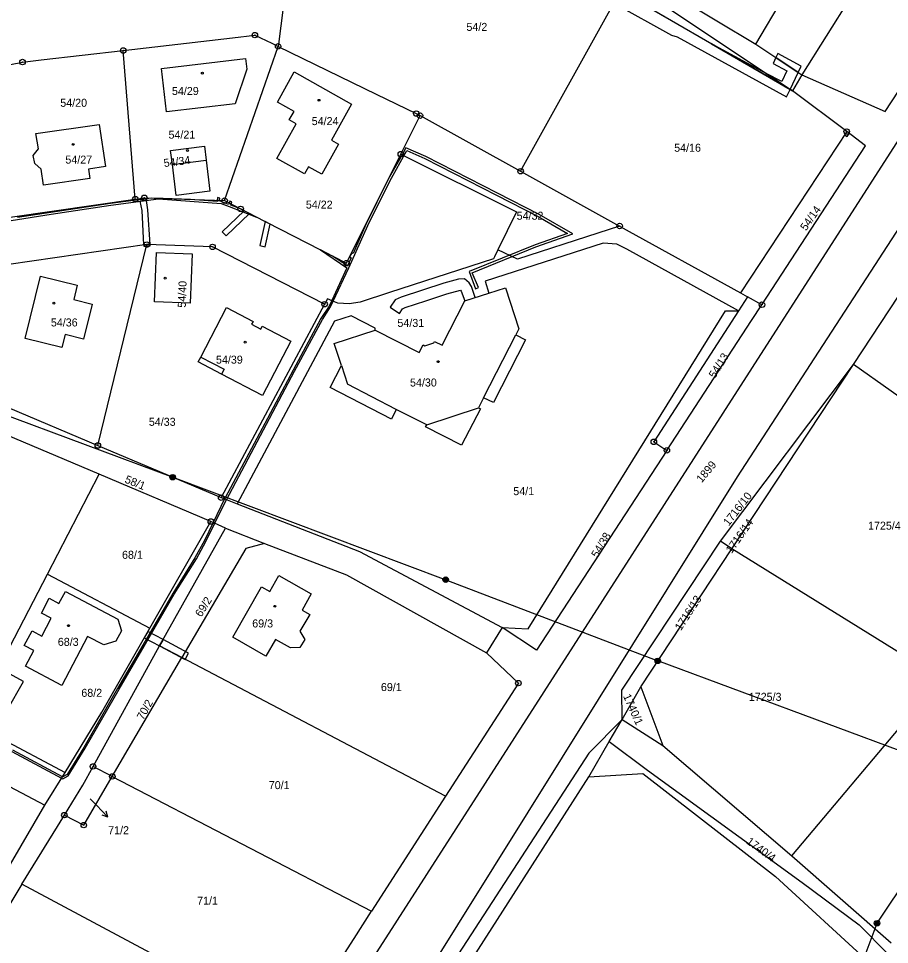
# Model space of a CAD drawing. Extents: x -587171 to -555306, y -1167727 to -1074732.
# Drawn here: x -559493.9 to -559335, y -1076599.6 to -1076430.8 of the extents above; entities that cross this region are included whole.
import ezdxf

# ---------------------------------------------------------------- set-up
doc = ezdxf.new("R2010")
doc.units = 0
for name, color, linetype in [('Hranice parcel', 7, 'Continuous'), ('Parcelní čísla', 7, 'Continuous'), ('Pop  PČ popisy', 7, 'Continuous'), ('Poz předměty', 7, 'Continuous'), ('Vnitřní kresba', 7, 'Continuous'), ('Věcná břemena k části', 7, 'Continuous'), ('Značky bodu BP', 7, 'Continuous'), ('Značky budov', 7, 'Continuous')]:
    doc.layers.add(name, color=color, linetype=linetype)

msp = doc.modelspace()

# ---------------------------------------------------------------- linework, layer by layer
at = {"layer": 'Hranice parcel'}
for p, q in [((-559295.54, -1076353.12), (-559351, -1076441.05)), ((-559359.39, -1076435.43), (-559344.86, -1076411.02)), ((-559385.89, -1076419.53), (-559359.39, -1076435.43)), ((-559352.65, -1076443.99), (-559384.02, -1076425.8)), ((-559456.26, -1076463.98), (-559446.5, -1076435.86)), ((-559359.39, -1076435.43), (-559351, -1076441.05)), ((-559472.55, -1076463.7), (-559474.75, -1076436.61)), ((-559351, -1076441.05), (-559352.65, -1076443.99)), ((-559342.79, -1076451.39), (-559352.65, -1076443.99)), ((-559424.11, -1076455.5), (-559420.61, -1076448.48)), ((-559420.61, -1076448.48), (-559402.27, -1076458.62)), ((-559342.79, -1076451.39), (-559362.14, -1076480.8)), ((-559402.27, -1076458.62), (-559384.2, -1076468.61)), ((-559495.36, -1076466.98), (-559472.55, -1076463.7)), ((-559384.2, -1076468.61), (-559362.14, -1076480.8)), ((-559479.38, -1076508.61), (-559470.45, -1076471.98)), ((-559362.52, -1076484.05), (-559382.91, -1076472.81)), ((-559360.87, -1076481.5), (-559362.52, -1076484.05)), ((-559362.14, -1076480.8), (-559360.87, -1076481.5)), ((-559358.25, -1076482.95), (-559360.87, -1076481.5)), ((-559438.02, -1076482.86), (-559456.89, -1076518.11)), ((-559400.9, -1076542.04), (-559364.92, -1076484.04)), ((-559364.92, -1076484.04), (-559362.52, -1076484.05)), ((-559365.81, -1076526.07), (-559341.55, -1076493.82)), ((-559363.74, -1076527.45), (-559341.55, -1076493.82)), ((-559495.73, -1076501.71), (-559479.38, -1076508.61)), ((-559479.13, -1076513.85), (-559497.95, -1076505.9)), ((-559479.38, -1076508.61), (-559456.89, -1076518.11)), ((-559488.54, -1076532.04), (-559479.13, -1076513.85)), ((-559458.77, -1076522.46), (-559479.13, -1076513.85)), ((-559453.98, -1076519.24), (-559431.64, -1076527.9)), ((-559469.9, -1076541.88), (-559458.77, -1076522.46)), ((-559468.14, -1076545.12), (-559456.12, -1076523.7)), ((-559456.12, -1076523.7), (-559458.77, -1076522.46)), ((-559456.12, -1076523.7), (-559448.96, -1076526.46)), ((-559448.96, -1076526.46), (-559452.38, -1076527.38)), ((-559448.96, -1076526.46), (-559434.02, -1076532.21)), ((-559363.74, -1076527.45), (-559365.81, -1076526.07)), ((-559452.38, -1076527.38), (-559464.04, -1076547.27)), ((-559431.64, -1076527.9), (-559405.64, -1076541.81)), ((-559380.33, -1076552.58), (-559363.74, -1076527.45)), ((-559325.62, -1076551.11), (-559363.74, -1076527.45)), ((-559496.26, -1076546.97), (-559488.54, -1076532.04)), ((-559488.54, -1076532.04), (-559469.9, -1076541.88)), ((-559434.02, -1076532.21), (-559408.49, -1076546.42)), ((-559405.64, -1076541.81), (-559408.49, -1076546.42)), ((-559405.64, -1076541.81), (-559400.9, -1076542.04)), ((-559480.25, -1076567.11), (-559468.14, -1076545.12)), ((-559464.04, -1076547.27), (-559468.14, -1076545.12)), ((-559476.74, -1076568.93), (-559464.04, -1076547.27)), ((-559415.94, -1076572.52), (-559464.04, -1076547.27)), ((-559352.77, -1076583.43), (-559325.62, -1076551.11)), ((-559383.77, -1076558.53), (-559380.33, -1076552.58)), ((-559380.33, -1076552.58), (-559376.32, -1076563.3)), ((-559502.55, -1076559.13), (-559485.32, -1076568.19)), ((-559386.1, -1076562.58), (-559383.77, -1076558.53)), ((-559383.77, -1076558.53), (-559376.32, -1076563.3)), ((-559389.81, -1076569), (-559386.1, -1076562.58)), ((-559376.32, -1076563.3), (-559352.77, -1076583.43)), ((-559505.11, -1076565.7), (-559489.07, -1076574.14)), ((-559476.74, -1076568.93), (-559480.25, -1076567.11)), ((-559489.07, -1076574.14), (-559485.32, -1076568.19)), ((-559481.94, -1076577.8), (-559476.74, -1076568.93)), ((-559476.74, -1076568.93), (-559429.44, -1076593.49)), ((-559444.21, -1076653.89), (-559389.81, -1076569)), ((-559415.94, -1076572.52), (-559429.44, -1076593.49)), ((-559503.32, -1076598.59), (-559489.07, -1076574.14)), ((-559493.23, -1076588.57), (-559485.49, -1076575.98)), ((-559485.49, -1076575.98), (-559481.94, -1076577.8)), ((-559352.77, -1076583.43), (-559334.65, -1076599.27)), ((-559493.23, -1076588.57), (-559507.12, -1076611.45)), ((-559443.38, -1076615.16), (-559493.23, -1076588.57))]:
    msp.add_line(p, q, dxfattribs=at)
for points in [[(-559351, -1076441.05), (-559335.79, -1076447.71), (-559279.35, -1076361.68)], [(-559607.03, -1076893.47), (-559583.72, -1076857.02), (-559527.43, -1076773.61), (-559475.25, -1076691.8), (-559419.98, -1076606.03), (-559362.73, -1076514.33), (-559323.56, -1076454.1), (-559268.76, -1076370.09)], [(-559529.43, -1076404.66), (-559482.86, -1076398.2), (-559441.57, -1076396.27), (-559435.57, -1076398.37), (-559414.99, -1076406.03), (-559382.52, -1076424.05), (-559352.65, -1076443.99)], [(-559441.99, -1076400.6), (-559446.45, -1076435.47), (-559446.5, -1076435.86)], [(-559402.27, -1076458.62), (-559385, -1076427.56), (-559384.02, -1076425.8)], [(-559474.75, -1076436.61), (-559454.8, -1076434.3), (-559450.73, -1076433.81), (-559447.66, -1076435.3), (-559446.5, -1076435.86)], [(-559446.5, -1076435.86), (-559428.63, -1076444.54), (-559421.29, -1076448.1), (-559420.61, -1076448.48)], [(-559497.59, -1076439.56), (-559493.12, -1076438.72), (-559489.72, -1076438.34), (-559474.75, -1076436.61)], [(-559452.2, -1076440.01), (-559454.35, -1076446.33), (-559466.85, -1076447.81), (-559467.79, -1076439.88), (-559452.45, -1076438.06), (-559452.2, -1076440.01)], [(-559436.77, -1076452.93), (-559435.46, -1076453.68), (-559438.52, -1076459.15), (-559440.97, -1076457.81), (-559441.66, -1076459.12), (-559446.73, -1076456.27), (-559443.19, -1076449.97), (-559444.47, -1076449.26), (-559443.6, -1076447.7), (-559446.64, -1076446), (-559443.59, -1076440.51), (-559433.1, -1076446.41), (-559436.77, -1076452.93)], [(-559489.72, -1076458.26), (-559490.87, -1076457.22), (-559491.15, -1076455.72), (-559490.23, -1076454.52), (-559490.66, -1076451.72), (-559479.13, -1076450.09), (-559478, -1076457.77), (-559481.08, -1076458.22), (-559480.87, -1076459.96), (-559489.31, -1076461.16), (-559489.72, -1076458.26)], [(-559341.55, -1076493.82), (-559318.54, -1076458.95), (-559313.06, -1076450.49)], [(-559358.25, -1076482.95), (-559339.34, -1076453.98), (-559342.79, -1076451.39)], [(-559459.64, -1076456.59), (-559458.93, -1076462.26), (-559465.07, -1076463.03), (-559465.74, -1076457.37), (-559466.11, -1076454.81), (-559459.94, -1076454.04), (-559459.64, -1076456.59)], [(-559456.26, -1076463.98), (-559453.34, -1076465.48), (-559434.01, -1076475.37), (-559424.11, -1076455.5)], [(-559424.11, -1076455.5), (-559403.03, -1076466.03), (-559406.4, -1076472.95)], [(-559472.55, -1076463.7), (-559470.9, -1076463.46), (-559456.26, -1076463.98)], [(-559384.2, -1076468.61), (-559388.16, -1076469.89), (-559402.86, -1076474.66), (-559406.4, -1076472.95)], [(-559470.45, -1076471.98), (-559504.05, -1076476.82), (-559542.47, -1076486.41)], [(-559438.02, -1076482.86), (-559458.45, -1076472.41), (-559470.45, -1076471.98)], [(-559406.4, -1076472.95), (-559407.01, -1076474.22), (-559407.19, -1076474.58), (-559426.17, -1076480.72), (-559431.54, -1076482.46), (-559433.53, -1076482.8), (-559435.58, -1076482.68), (-559436.51, -1076482.28), (-559437.48, -1076481.86), (-559438.02, -1076482.86)], [(-559382.91, -1076472.81), (-559384.7, -1076471.91), (-559387.2, -1076471.73), (-559408.76, -1076478.64), (-559408.07, -1076480.85)], [(-559468.69, -1076473.42), (-559462.19, -1076473.68), (-559462.55, -1076482.69), (-559469.06, -1076482.42), (-559468.69, -1076473.42)], [(-559485.33, -1076488.39), (-559485.93, -1076490.72), (-559492.63, -1076489.08), (-559489.85, -1076477.76), (-559483.16, -1076479.4), (-559483.77, -1076482.01), (-559480.42, -1076482.84), (-559481.97, -1076489.21), (-559485.33, -1076488.39)], [(-559408.07, -1076480.85), (-559405, -1076479.86), (-559402.59, -1076487.33), (-559403.13, -1076488.42), (-559401.38, -1076489.32), (-559407.22, -1076500.76), (-559409.02, -1076499.95), (-559409.94, -1076501.74), (-559409.61, -1076501.93), (-559413.03, -1076508.52), (-559419.59, -1076505.19), (-559419.4, -1076504.85), (-559424.96, -1076502.02), (-559425.84, -1076503.79), (-559436.98, -1076498.04), (-559434.96, -1076494.04), (-559436.26, -1076489.99), (-559428.8, -1076487.56)], [(-559428.8, -1076487.56), (-559420.76, -1076491.67), (-559420.04, -1076490.29), (-559419.75, -1076490.42), (-559418.1, -1076489.89), (-559417.96, -1076489.63), (-559416.57, -1076490.32), (-559412.44, -1076482.27), (-559408.07, -1076480.85)], [(-559375.58, -1076509.5), (-559360.13, -1076485.83), (-559358.25, -1076482.95)], [(-559449.37, -1076499.51), (-559456.83, -1076495.6), (-559461.08, -1076493.38), (-559460.61, -1076492.5), (-559455.89, -1076483.44), (-559451.05, -1076485.98), (-559451.33, -1076486.51), (-559449.65, -1076487.39), (-559449.38, -1076486.86), (-559444.18, -1076489.58), (-559449.37, -1076499.51)], [(-559362.52, -1076484.05), (-559377.97, -1076507.94), (-559375.58, -1076509.5)], [(-559428.8, -1076487.56), (-559428.82, -1076487.2), (-559433.15, -1076484.97), (-559436.24, -1076485.94), (-559453.98, -1076519.24)], [(-559299.73, -1076520.3), (-559320.93, -1076508.42), (-559341.55, -1076493.82)], [(-559375.58, -1076509.5), (-559399.34, -1076545.9), (-559405.64, -1076541.81)], [(-559456.89, -1076518.11), (-559455.81, -1076518.53), (-559453.98, -1076519.24)], [(-559383.77, -1076558.53), (-559383.83, -1076553.18), (-559365.81, -1076526.07)], [(-559440.46, -1076535.67), (-559442.13, -1076538.6), (-559440.71, -1076539.41), (-559442.51, -1076542.46), (-559441.64, -1076543.99), (-559442.51, -1076545.45), (-559444.21, -1076545.49), (-559446.96, -1076543.94), (-559448.74, -1076546.99), (-559454.75, -1076543.53), (-559449.5, -1076534.38), (-559448.01, -1076535.23), (-559446.34, -1076532.29), (-559440.46, -1076535.67)], [(-559487.89, -1076540.11), (-559489.67, -1076539.17), (-559488.23, -1076536.45), (-559486.47, -1076537.39), (-559485.3, -1076535.2), (-559475.73, -1076540.26), (-559475.07, -1076542.39), (-559476.07, -1076544.3), (-559478.26, -1076544.94), (-559481.29, -1076543.41), (-559485.96, -1076552.34), (-559492.55, -1076548.83), (-559491.05, -1076546), (-559492.8, -1076545.07), (-559491.38, -1076542.4), (-559489.61, -1076543.34), (-559487.89, -1076540.11)], [(-559485.32, -1076568.19), (-559478.68, -1076557.2), (-559469.9, -1076541.88)], [(-559408.49, -1076546.42), (-559402.67, -1076551.92), (-559415.94, -1076572.52)], [(-559496.71, -1076549.53), (-559499.61, -1076554.86), (-559495.91, -1076556.88), (-559492.94, -1076551.61), (-559496.71, -1076549.53)], [(-559383.77, -1076558.53), (-559389.83, -1076564.66), (-559418.99, -1076609.61), (-559442.78, -1076645.59), (-559446.74, -1076652.48), (-559462.67, -1076678.14), (-559480.05, -1076709.84)], [(-559386.1, -1076562.58), (-559379.12, -1076567.76), (-559350.9, -1076588.29), (-559340.49, -1076595.99), (-559324.64, -1076612.04), (-559313.62, -1076622.95), (-559303.17, -1076634.5)], [(-559485.49, -1076575.98), (-559482.14, -1076570.54), (-559480.25, -1076567.11)], [(-559389.81, -1076569), (-559379.95, -1076568.39), (-559355.76, -1076587.17), (-559338.67, -1076602.87), (-559308.6, -1076639.92), (-559300.81, -1076674.62)], [(-559443.38, -1076615.16), (-559432.64, -1076598.47), (-559429.44, -1076593.49)]]:
    msp.add_lwpolyline(points, dxfattribs=at)
at = {"layer": 'Pop  PČ popisy'}
for p, q in [((-559480.77, -1076572.99), (-559479.63, -1076574.19)), ((-559479.63, -1076574.19), (-559477.55, -1076576.35)), ((-559477.55, -1076576.35), (-559478.6, -1076575.98)), ((-559477.55, -1076576.35), (-559477.88, -1076575.28))]:
    msp.add_line(p, q, dxfattribs=at)
at = {"layer": 'Poz předměty'}
for p, q in [((-559537.47, -1076770.43), (-559333.23, -1076452.78)), ((-559539.87, -1076486.75), (-559465.72, -1076514.39)), ((-559465.72, -1076514.39), (-559415.93, -1076533.07)), ((-559415.93, -1076533.07), (-559377.26, -1076547.87)), ((-559319.58, -1076569.27), (-559377.26, -1076547.87)), ((-559337.26, -1076595.69), (-559319.58, -1076569.27)), ((-559357.53, -1076650.03), (-559337.26, -1076595.69))]:
    msp.add_line(p, q, dxfattribs=at)
for centre, radius in [((-559465.72, -1076514.39), 0.5), ((-559465.72, -1076514.39), 0.4), ((-559465.72, -1076514.39), 0.3), ((-559465.72, -1076514.39), 0.2), ((-559465.72, -1076514.39), 0.1), ((-559415.93, -1076533.07), 0.5), ((-559415.93, -1076533.07), 0.4), ((-559415.93, -1076533.07), 0.3), ((-559415.93, -1076533.07), 0.2), ((-559415.93, -1076533.07), 0.1), ((-559377.26, -1076547.87), 0.5), ((-559377.26, -1076547.87), 0.4), ((-559377.26, -1076547.87), 0.3), ((-559377.26, -1076547.87), 0.2), ((-559377.26, -1076547.87), 0.1), ((-559337.26, -1076595.69), 0.5), ((-559337.26, -1076595.69), 0.4), ((-559337.26, -1076595.69), 0.3), ((-559337.26, -1076595.69), 0.2), ((-559337.26, -1076595.69), 0.1)]:
    msp.add_circle(centre, radius, dxfattribs=at)
at = {"layer": 'Vnitřní kresba'}
for p, q in [((-559465.74, -1076457.37), (-559459.64, -1076456.59)), ((-559409.02, -1076499.95), (-559403.13, -1076488.42)), ((-559460.61, -1076492.5), (-559456.36, -1076494.72)), ((-559456.36, -1076494.72), (-559456.83, -1076495.6)), ((-559434.96, -1076494.04), (-559433.87, -1076497.45)), ((-559424.96, -1076502.02), (-559433.87, -1076497.45)), ((-559419.4, -1076504.85), (-559409.94, -1076501.74))]:
    msp.add_line(p, q, dxfattribs=at)
at = {"layer": 'Věcná břemena k části'}
for points in [[(-559353.75, -1076445.05), (-559353.12, -1076443.72), (-559367.42, -1076435.42), (-559384.02, -1076425.8), (-559385.24, -1076428), (-559374.75, -1076433.82), (-559373.73, -1076434.09)], [(-559367.42, -1076435.42), (-559353.12, -1076443.72), (-559353.1, -1076443.69), (-559357.47, -1076440.78)], [(-559351.64, -1076440.62), (-559351.09, -1076439.46), (-559355.38, -1076437.17), (-559355.71, -1076437.89)], [(-559357.47, -1076440.78), (-559353.1, -1076443.69), (-559351.64, -1076440.62), (-559355.71, -1076437.89), (-559356.22, -1076438.99), (-559353.72, -1076440.33), (-559354.65, -1076442.29)], [(-559342.79, -1076451.39), (-559343.17, -1076451.97), (-559342.71, -1076452.28), (-559342.34, -1076451.73)], [(-559471.69, -1076464.08), (-559471.35, -1076465.78), (-559471.03, -1076472.06), (-559470.45, -1076471.98), (-559469.86, -1076472), (-559470.24, -1076465.65), (-559470.53, -1076463.93)], [(-559457.59, -1076463.93), (-559457.18, -1076463.95), (-559457.13, -1076463.5), (-559457.55, -1076463.38)], [(-559455.43, -1076464.41), (-559455.06, -1076464.6), (-559454.92, -1076464.22), (-559455.31, -1076464.07)], [(-559456, -1076470.41), (-559451.73, -1076466.3), (-559452.68, -1076465.82), (-559456.7, -1076469.69)], [(-559448.83, -1076472.4), (-559447.93, -1076468.25), (-559448.85, -1076467.78), (-559449.81, -1076472.18)], [(-559471.02, -1076472.3), (-559470.52, -1076472.26), (-559470.45, -1076471.98), (-559471.03, -1076472.06)], [(-559469.85, -1076472.23), (-559469.86, -1076472), (-559470.45, -1076471.98), (-559470.52, -1076472.26)], [(-559424.36, -1076484.52), (-559423.78, -1076483.67), (-559423.34, -1076483.47), (-559419.54, -1076482.23), (-559415.72, -1076480.95), (-559413.25, -1076480.31), (-559413.08, -1076480.48), (-559412.44, -1076482.27), (-559410.54, -1076481.65), (-559411.22, -1076479.64), (-559411.62, -1076478.95), (-559412.51, -1076478.21), (-559413.59, -1076478.31), (-559416.3, -1076479.01), (-559420.18, -1076480.31), (-559424.08, -1076481.57), (-559425.14, -1076482.05), (-559426.04, -1076483.38)], [(-559470.25, -1076542.49), (-559470.91, -1076543.64), (-559468.14, -1076545.12), (-559467.49, -1076543.97)], [(-559463.44, -1076547.59), (-559462.83, -1076546.46), (-559467.49, -1076543.97), (-559468.14, -1076545.12)]]:
    msp.add_lwpolyline(points, close=True, dxfattribs=at)
for points in [[(-559495.04, -1076564.39), (-559485.98, -1076569.24), (-559485.76, -1076569.36), (-559484.77, -1076568.8), (-559481.69, -1076563.79), (-559475.52, -1076553.02), (-559470.93, -1076545.19), (-559465.43, -1076535.73), (-559461.41, -1076529.25), (-559459.66, -1076526.09), (-559458.06, -1076522.79), (-559456.72, -1076520.05), (-559455.9, -1076518.49), (-559448.64, -1076504.75), (-559443.52, -1076495.03), (-559438.43, -1076485.65), (-559436.93, -1076483.35), (-559436.44, -1076482.31), (-559433.57, -1076476.23), (-559430.14, -1076468.49), (-559426.11, -1076460.41), (-559423, -1076454.85), (-559419.72, -1076456.31), (-559406.67, -1076462.96), (-559399.09, -1076466.89), (-559393.72, -1076469.94), (-559399.61, -1076472.04), (-559411.64, -1076476.91), (-559410.52, -1076480.03), (-559409.92, -1076479.83), (-559411.12, -1076477.13), (-559399.47, -1076472.42), (-559392.76, -1076470.02), (-559398.91, -1076466.53), (-559406.49, -1076462.6), (-559419.54, -1076455.95), (-559423.18, -1076454.33), (-559423.89, -1076455.61), (-559426.46, -1076460.21), (-559430.51, -1076468.34), (-559432.83, -1076473.59), (-559433.07, -1076473.48), (-559433.45, -1076474.25), (-559433.19, -1076474.38), (-559433.86, -1076475.89), (-559436.56, -1076474.07), (-559438.79, -1076472.92), (-559433.94, -1076476.2), (-559436.72, -1076482.19), (-559437.19, -1076483.21), (-559438.69, -1076485.49), (-559443.78, -1076494.89), (-559448.9, -1076504.61), (-559456.16, -1076518.12), (-559456.27, -1076518.35), (-559458.34, -1076522.66), (-559459.92, -1076525.95), (-559461.67, -1076529.09), (-559465.69, -1076535.57), (-559471.19, -1076545.03), (-559475.78, -1076552.88), (-559481.95, -1076563.63), (-559484.99, -1076568.58), (-559485.76, -1076569.02), (-559485.82, -1076568.99), (-559494.9, -1076564.13)], [(-559495.21, -1076467.61), (-559487.92, -1076466.46), (-559477.03, -1076464.8), (-559468.29, -1076463.63), (-559456.9, -1076464.47), (-559455.45, -1076465.03), (-559450.43, -1076466.97), (-559453.34, -1076465.48), (-559455.15, -1076464.82), (-559455.06, -1076464.6), (-559455.43, -1076464.41), (-559455.53, -1076464.68), (-559457.19, -1076464.03), (-559457.18, -1076463.95), (-559457.59, -1076463.93), (-559457.61, -1076464.12), (-559462.5, -1076463.76), (-559467.48, -1076463.58), (-559469.61, -1076463.51), (-559477.07, -1076464.5), (-559487.96, -1076466.16), (-559494.03, -1076467.06)]]:
    msp.add_lwpolyline(points, dxfattribs=at)
at = {"layer": 'Značky bodu BP'}
for centre, radius in [((-559450.73, -1076433.81), 0.5), ((-559450.73, -1076433.81), 0.0303), ((-559446.5, -1076435.86), 0.5), ((-559446.5, -1076435.86), 0.0303), ((-559474.75, -1076436.61), 0.5), ((-559474.75, -1076436.61), 0.0303), ((-559493.12, -1076438.72), 0.5), ((-559493.12, -1076438.72), 0.0303), ((-559421.29, -1076448.1), 0.5), ((-559421.29, -1076448.1), 0.0303), ((-559420.61, -1076448.48), 0.5), ((-559420.61, -1076448.48), 0.0303), ((-559342.79, -1076451.39), 0.5), ((-559342.79, -1076451.39), 0.0303), ((-559424.11, -1076455.5), 0.5), ((-559424.11, -1076455.5), 0.0303), ((-559402.27, -1076458.62), 0.5), ((-559402.27, -1076458.62), 0.0303), ((-559470.9, -1076463.46), 0.5), ((-559472.55, -1076463.7), 0.5), ((-559472.55, -1076463.7), 0.0303), ((-559470.9, -1076463.46), 0.0303), ((-559456.26, -1076463.98), 0.5), ((-559456.26, -1076463.98), 0.0303), ((-559453.34, -1076465.48), 0.5), ((-559453.34, -1076465.48), 0.0303), ((-559384.2, -1076468.61), 0.5), ((-559384.2, -1076468.61), 0.0303), ((-559470.45, -1076471.98), 0.5), ((-559470.45, -1076471.98), 0.0303), ((-559458.45, -1076472.41), 0.5), ((-559458.45, -1076472.41), 0.0303), ((-559434.01, -1076475.37), 0.5), ((-559434.01, -1076475.37), 0.0303), ((-559438.02, -1076482.86), 0.5), ((-559438.02, -1076482.86), 0.0303), ((-559358.25, -1076482.95), 0.5), ((-559358.25, -1076482.95), 0.0303), ((-559479.38, -1076508.61), 0.5), ((-559377.97, -1076507.94), 0.5), ((-559377.97, -1076507.94), 0.0303), ((-559479.38, -1076508.61), 0.0303), ((-559375.58, -1076509.5), 0.5), ((-559375.58, -1076509.5), 0.0303), ((-559456.89, -1076518.11), 0.5), ((-559456.89, -1076518.11), 0.0303), ((-559458.77, -1076522.46), 0.5), ((-559458.77, -1076522.46), 0.0303), ((-559402.67, -1076551.92), 0.5), ((-559402.67, -1076551.92), 0.0303), ((-559480.25, -1076567.11), 0.5), ((-559480.25, -1076567.11), 0.0303), ((-559476.74, -1076568.93), 0.5), ((-559476.74, -1076568.93), 0.0303), ((-559485.49, -1076575.98), 0.5), ((-559485.49, -1076575.98), 0.0303), ((-559481.94, -1076577.8), 0.5), ((-559481.94, -1076577.8), 0.0303)]:
    msp.add_circle(centre, radius, dxfattribs=at)
at = {"layer": 'Značky budov'}
for centre in [(-559460.32, -1076440.73), (-559439.04, -1076445.69), (-559483.9, -1076453.72), (-559463.03, -1076454.85), (-559467.12, -1076478.12), (-559487.38, -1076482.67), (-559452.51, -1076489.76), (-559417.32, -1076493.33), (-559447.09, -1076537.92), (-559484.74, -1076541.45)]:
    msp.add_circle(centre, 0.175, dxfattribs=at)

# ---------------------------------------------------------------- texts
at = {"layer": 'Parcelní čísla'}
for s, p in [('54/2', (-559412.15, -1076433.04)), ('54/29', (-559465.86, -1076444.72)), ('54/20', (-559486.23, -1076446.87)), ('54/24', (-559440.37, -1076450.21)), ('54/21', (-559466.49, -1076452.68)), ('54/16', (-559374.26, -1076455.07)), ('54/27', (-559485.3, -1076457.23)), ('54/22', (-559441.44, -1076465.43)), ('54/32', (-559402.99, -1076467.46)), ('54/36', (-559487.95, -1076486.91)), ('54/31', (-559424.74, -1076487)), ('54/39', (-559457.83, -1076493.69)), ('54/30', (-559422.44, -1076497.86)), ('54/33', (-559470.08, -1076505.02)), ('54/1', (-559403.6, -1076517.66)), ('1725/4', (-559338.9, -1076523.95)), ('68/1', (-559474.97, -1076529.26)), ('69/3', (-559451.22, -1076541.77)), ('68/3', (-559486.68, -1076545.13)), ('69/1', (-559427.75, -1076553.37)), ('68/2', (-559482.39, -1076554.42)), ('1725/3', (-559360.65, -1076555.15)), ('70/1', (-559448.2, -1076571.24)), ('71/2', (-559477.5, -1076579.46)), ('71/1', (-559461.27, -1076592.3))]:
    msp.add_text(s, height=1.46, dxfattribs=at).set_placement(p)
for s, rotation, p in [('54/34', 7, (-559467.28, -1076457.86)), ('54/14', 55, (-559350.2, -1076469.59)), ('54/40', 88, (-559463.35, -1076483.51)), ('54/13', 58, (-559366.82, -1076496.48)), ('1899', 50, (-559369.24, -1076515.51)), ('58/1', 338, (-559474.59, -1076515.33)), ('1716/10', 52, (-559364.31, -1076523.39)), ('1716/14', 55, (-559363.78, -1076528.41)), ('54/38', 59, (-559388.24, -1076529.21)), ('69/2', 58, (-559460.51, -1076539.99)), ('1716/13', 57, (-559373.03, -1076542.47)), ('1740/1', 294, (-559383.61, -1076554.28)), ('70/2', 61, (-559471.1, -1076558.76)), ('1740/4', 324, (-559361.22, -1076581.07))]:
    msp.add_text(s, height=1.46, rotation=rotation, dxfattribs=at).set_placement(p)

doc.saveas('drawing.dxf')
